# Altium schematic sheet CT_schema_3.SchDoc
size 296 x 169 mm
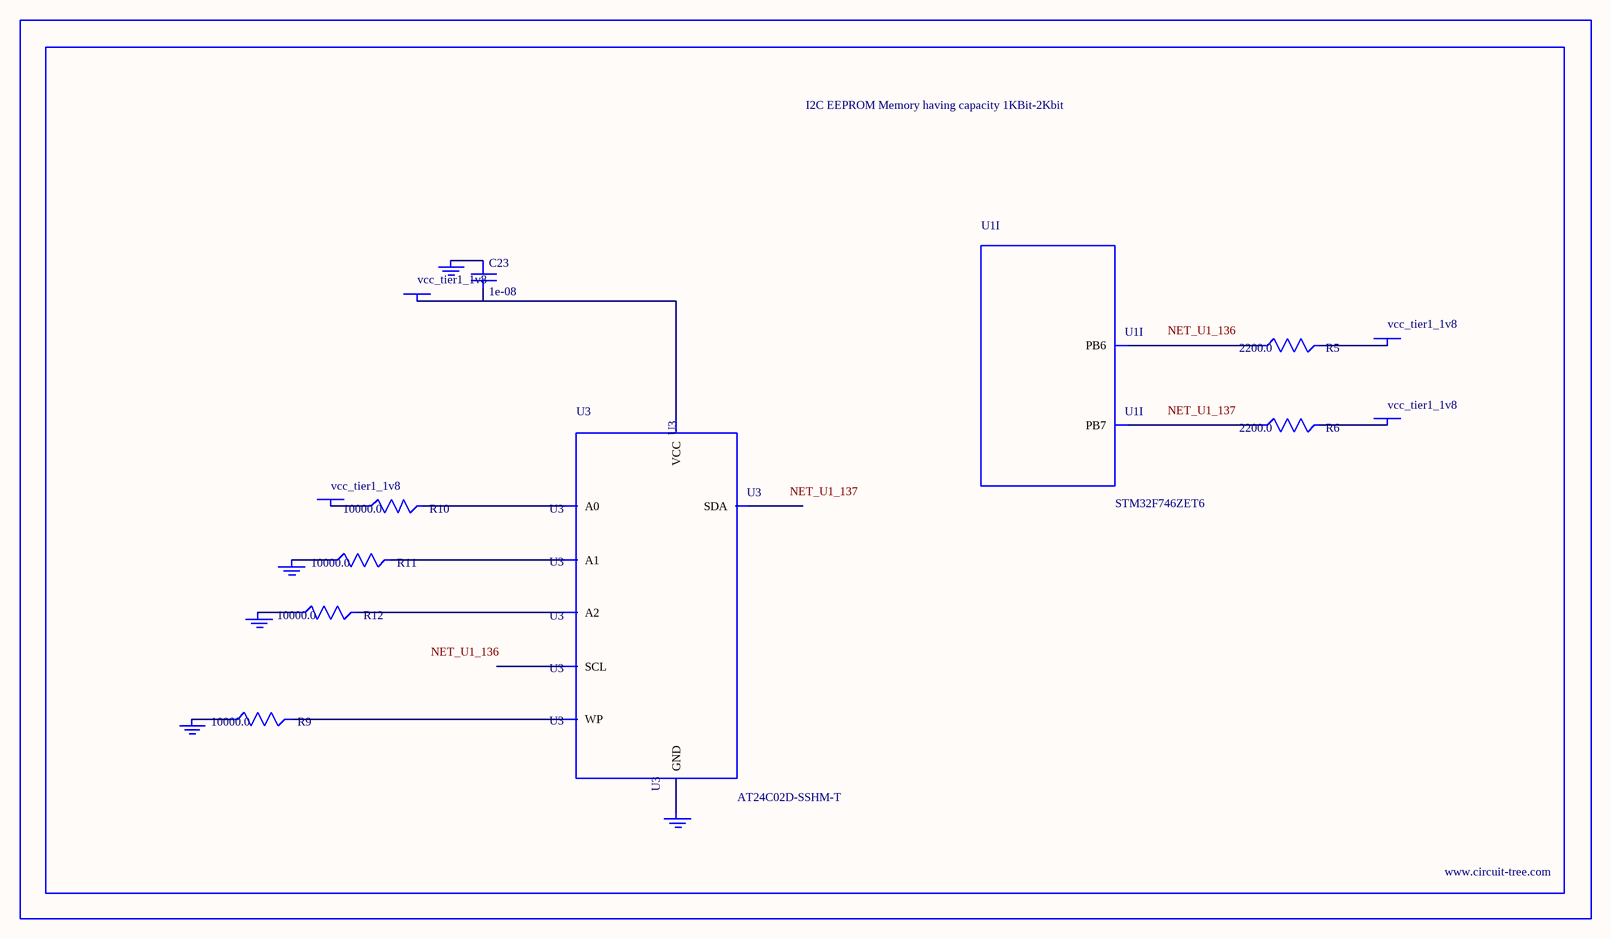
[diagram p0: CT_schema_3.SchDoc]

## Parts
BORDER2  (no value)
C23  1e-08  [C0402]
GND_INSTANCE_2_0  (no value)
GND_INSTANCE_2_1  (no value)
GND_INSTANCE_2_2  (no value)
GND_INSTANCE_2_3  (no value)
GND_INSTANCE_2_4  (no value)
POWER_INSTANCE_2_0  vcc_tier1_1v8
POWER_INSTANCE_2_1  vcc_tier1_1v8
POWER_INSTANCE_2_2  vcc_tier1_1v8
POWER_INSTANCE_2_3  vcc_tier1_1v8
R5  2200.0  [R0603]
R6  2200.0  [R0603]
R9  10000.0  [R0603]
R10  10000.0  [R0603]
R11  10000.0  [R0603]
R12  10000.0  [R0603]
U1  STM32F746ZET6  [LQFP144]  (part I of 13)
U3  AT24C02D-SSHM-T  [AT24C02D]

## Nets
NetC23_1: C23.1 GND_INSTANCE_2_3.0(GND)
NetC23_2: C23.2 POWER_INSTANCE_2_1.0(PWR) U3.8(VCC)
NetGND_INSTANCE_2_0_0: GND_INSTANCE_2_0.0(GND) R11.1
NetGND_INSTANCE_2_1_0: GND_INSTANCE_2_1.0(GND) R12.1
NetGND_INSTANCE_2_2_0: GND_INSTANCE_2_2.0(GND) R9.1
NetGND_INSTANCE_2_4_0: GND_INSTANCE_2_4.0(GND) U3.4(GND)
NetPOWER_INSTANCE_2_0_0: POWER_INSTANCE_2_0.0(PWR) R10.1
NetPOWER_INSTANCE_2_2_0: POWER_INSTANCE_2_2.0(PWR) R5.2
NetPOWER_INSTANCE_2_3_0: POWER_INSTANCE_2_3.0(PWR) R6.2
NetR5_1: R5.1 U1.136(PB6)
NetR6_1: R6.1 U1.137(PB7)
NetR9_2: R9.2 U3.7(WP)
NetR10_2: R10.2 U3.1(A0)
NetR11_2: R11.2 U3.2(A1)
NetR12_2: R12.2 U3.3(A2)

Not connected (* = marked no-connect by the designer): U3 5(SDA) 6(SCL)

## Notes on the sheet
- Labels drawn without touching a wire or pin: NET_U1_136, NET_U1_137

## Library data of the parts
BORDER2 = BORDER_PAGE2
C23 = C0402C103K3RAC
GND_INSTANCE_2_0-GND_INSTANCE_2_4 = GND
POWER_INSTANCE_2_0-POWER_INSTANCE_2_3 = PWR
R5 R6 = RC0603JR-072K2L
R9-R12 = RC0603JR-0710KL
